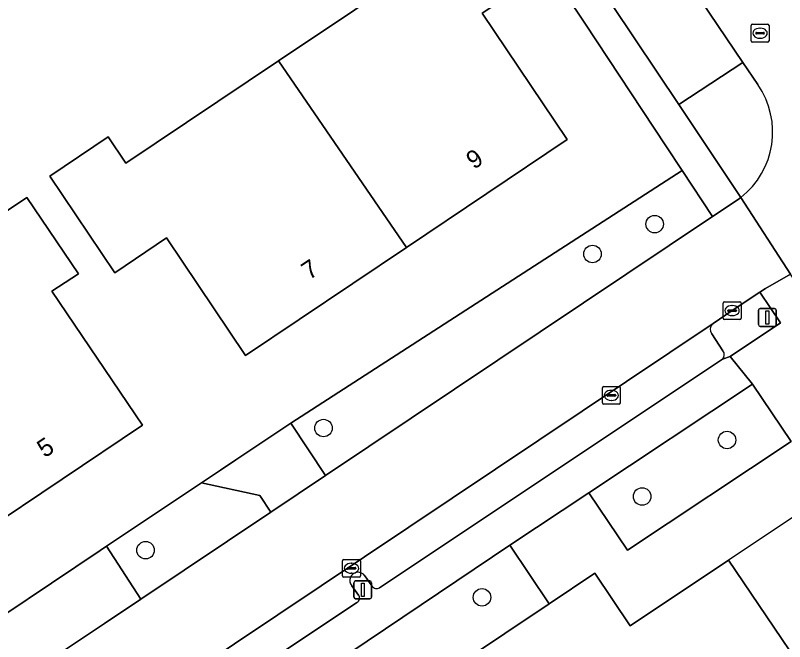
# Model space of a CAD drawing. Extents: x 158793 to 159888, y 384317 to 385256.
# Drawn here: x 158866.24 to 158909.23, y 384582.61 to 384617.61 of the extents above; entities that cross this region are included whole.
import ezdxf

# ---------------------------------------------------------------- set-up
doc = ezdxf.new("R2010")
doc.units = 0
for name, color, linetype in [('IMGEO_Berm_groen', 7, 'Continuous'), ('IMGEO_Boom', 7, 'Continuous'), ('IMGEO_Erf', 7, 'Continuous'), ('IMGEO_Groenvoorziening', 7, 'Continuous'), ('IMGEO_Inrit_open', 7, 'Continuous'), ('IMGEO_Kolk', 7, 'Continuous'), ('IMGEO_Lichtmast', 7, 'Continuous'), ('IMGEO_Pand', 7, 'Continuous'), ('IMGEO_Pand_nummerreeks', 7, 'Continuous'), ('IMGEO_Pand_overbouw', 7, 'Continuous'), ('IMGEO_Parkeervlak_open', 7, 'Continuous'), ('IMGEO_Rijbaan_lokaal_open', 7, 'Continuous'), ('IMGEO_Rioolput', 7, 'Continuous'), ('IMGEO_Voetpad_open', 7, 'Continuous')]:
    doc.layers.add(name, color=color, linetype=linetype)

msp = doc.modelspace()

# ---------------------------------------------------------------- linework, layer by layer
at = {"layer": 'IMGEO_Berm_groen'}
msp.add_lwpolyline([(158907.727, 384613.741), (158906.885, 384614.978), (158903.319, 384612.632), (158906.772, 384607.422)], dxfattribs=at)
msp.add_arc((158903.915, 384611.086), 4.646, 307.9533, 34.8584, dxfattribs=at)
at = {"layer": 'IMGEO_Boom'}
for centre in [(158901.963, 384605.942), (158898.492, 384604.271), (158883.458, 384594.542), (158906.011, 384593.873), (158901.264, 384590.718), (158873.516, 384587.717), (158892.319, 384585.079)]:
    msp.add_circle(centre, 0.489, dxfattribs=at)
at = {"layer": 'IMGEO_Erf'}
msp.add_lwpolyline([(158815.511, 384607.239), (158824.8, 384593.502), (158838.699, 384572.93), (158841.845, 384568.15), (158844.791, 384570.111), (158846.183, 384571.037), (158851.961, 384574.901), (158852.64, 384575.355), (158857.172, 384578.386), (158862.362, 384581.922), (158862.863, 384582.253), (158870.987, 384587.696), (158871.33, 384587.937), (158876.65, 384591.488), (158877.708, 384592.194), (158878.556, 384592.76), (158881.626, 384594.81), (158903.507, 384608.931), (158902.593, 384610.317), (158898.058, 384617.173), (158883.161, 384639.419), (158896.259, 384659.409)], dxfattribs=at)
for points in [[(158890.862, 384623.871), (158894.156, 384618.966), (158892.321, 384617.734), (158897.071, 384610.661), (158888.089, 384604.629), (158879.107, 384598.597), (158874.693, 384605.179), (158871.792, 384603.213), (158868.157, 384608.628), (158871.419, 384610.825), (158872.409, 384609.35), (158880.94, 384615.071), (158889.47, 384620.792), (158888.486, 384622.266)], [(158856.444, 384600.417), (158866.89, 384607.424), (158869.764, 384603.17), (158868.286, 384602.201), (158873.34, 384594.709), (158864.344, 384588.665), (158855.349, 384582.621), (158849.856, 384590.796), (158848.386, 384589.809), (158845.998, 384593.41)]]:
    msp.add_lwpolyline(points, close=True, dxfattribs=at)
at = {"layer": 'IMGEO_Groenvoorziening'}
for points in [[(158905.203, 384606.361), (158903.507, 384608.931), (158881.626, 384594.81), (158883.58, 384591.897)], [(158909.588, 384593.8), (158907.433, 384597), (158898.293, 384590.919), (158900.445, 384587.717)], [(158880.518, 384589.849), (158879.9, 384590.767), (158876.65, 384591.488), (158871.33, 384587.937), (158873.243, 384584.982)], [(158896.066, 384584.721), (158893.869, 384587.99), (158878.954, 384577.951), (158881.101, 384574.689)]]:
    msp.add_lwpolyline(points, close=True, dxfattribs=at)
for points in [[(158907.845, 384602.133), (158906.293, 384601.105), (158905.226, 384600.389), (158905.186, 384600.352)], [(158905.751, 384598.386), (158906.179, 384598.54), (158909.004, 384600.431), (158907.845, 384602.133)], [(158905.152, 384599.809), (158905.78, 384598.862)]]:
    msp.add_lwpolyline(points, dxfattribs=at)
for centre, radius, start, end in [((158905.487, 384600.061), 0.419, 135.8936, 216.9406), ((158905.5, 384598.64), 0.357, 314.6782, 38.349)]:
    msp.add_arc(centre, radius, start, end, dxfattribs=at)
at = {"layer": 'IMGEO_Inrit_open'}
msp.add_lwpolyline([(158871.218, 384583.628), (158873.243, 384584.982), (158871.33, 384587.937), (158870.987, 384587.696), (158862.863, 384582.253), (158862.362, 384581.922), (158864.28, 384578.99), (158865.964, 384580.114), (158866.578, 384580.525)], close=True, dxfattribs=at)
at = {"layer": 'IMGEO_Kolk'}
for p, q in [((158905.792, 384600.679), (158905.792, 384601.531)), ((158905.867, 384601.605), (158906.719, 384601.605)), ((158906.28, 384601.385), (158906.305, 384601.385)), ((158906.793, 384601.531), (158906.793, 384600.679)), ((158906.051, 384601.099), (158906.051, 384601.111)), ((158906.489, 384601.062), (158906.091, 384601.062)), ((158906.094, 384601.148), (158906.492, 384601.148)), ((158906.303, 384600.825), (158906.278, 384600.825)), ((158906.535, 384601.111), (158906.535, 384601.099)), ((158906.719, 384600.605), (158905.867, 384600.605)), ((158899.045, 384595.945), (158899.045, 384596.797)), ((158899.12, 384596.871), (158899.972, 384596.871)), ((158899.533, 384596.651), (158899.558, 384596.651)), ((158900.046, 384596.797), (158900.046, 384595.945)), ((158899.304, 384596.365), (158899.304, 384596.377)), ((158899.742, 384596.328), (158899.344, 384596.328)), ((158899.347, 384596.414), (158899.745, 384596.414)), ((158899.556, 384596.091), (158899.531, 384596.091)), ((158899.788, 384596.377), (158899.788, 384596.365)), ((158899.972, 384595.871), (158899.12, 384595.871)), ((158884.523, 384586.278), (158884.523, 384587.13)), ((158884.598, 384587.204), (158885.45, 384587.204)), ((158885.524, 384587.13), (158885.524, 384586.278)), ((158884.782, 384586.698), (158884.782, 384586.71)), ((158885.22, 384586.661), (158884.822, 384586.661)), ((158884.825, 384586.747), (158885.223, 384586.747)), ((158885.011, 384586.984), (158885.036, 384586.984)), ((158885.266, 384586.71), (158885.266, 384586.698)), ((158885.45, 384586.204), (158884.598, 384586.204)), ((158885.034, 384586.424), (158885.009, 384586.424))]:
    msp.add_line(p, q, dxfattribs=at)
for points in [[(158905.792, 384600.679), (158905.792, 384601.531)], [(158905.867, 384601.605), (158906.719, 384601.605)], [(158906.793, 384601.531), (158906.793, 384600.679)], [(158906.719, 384600.605), (158905.867, 384600.605)], [(158899.045, 384595.945), (158899.045, 384596.797)], [(158899.12, 384596.871), (158899.972, 384596.871)], [(158900.046, 384596.797), (158900.046, 384595.945)], [(158899.972, 384595.871), (158899.12, 384595.871)], [(158884.523, 384586.278), (158884.523, 384587.13)], [(158884.598, 384587.204), (158885.45, 384587.204)], [(158885.524, 384587.13), (158885.524, 384586.278)], [(158885.45, 384586.204), (158884.598, 384586.204)]]:
    msp.add_lwpolyline(points, dxfattribs=at)
for centre, radius, start, end in [((158905.869, 384601.529), 0.0765, 91.552, 178.448), ((158905.869, 384601.529), 0.0765, 91.552, 178.448), ((158906.717, 384601.529), 0.0765, 1.552, 88.448), ((158906.717, 384601.529), 0.0765, 1.552, 88.448), ((158906.091, 384601.108), 0.0403, 85.8775, 175.7526), ((158906.088, 384601.098), 0.0366, 178.938, 274.7102), ((158906.492, 384601.105), 0.043, 264.8664, 352.4533), ((158906.496, 384601.11), 0.0386, 1.7309, 96.639), ((158905.869, 384600.681), 0.0765, 181.552, 268.448), ((158905.869, 384600.681), 0.0765, 181.552, 268.448), ((158906.717, 384600.681), 0.0765, 271.552, 358.448), ((158906.717, 384600.681), 0.0765, 271.552, 358.448), ((158899.122, 384596.795), 0.0765, 91.552, 178.448), ((158899.122, 384596.795), 0.0765, 91.552, 178.448), ((158899.97, 384596.795), 0.0765, 1.552, 88.448), ((158899.97, 384596.795), 0.0765, 1.552, 88.448), ((158899.344, 384596.374), 0.0403, 85.8775, 175.7526), ((158899.341, 384596.364), 0.0366, 178.938, 274.7102), ((158899.745, 384596.371), 0.043, 264.8664, 352.4533), ((158899.749, 384596.376), 0.0386, 1.7309, 96.639), ((158899.122, 384595.947), 0.0765, 181.552, 268.448), ((158899.122, 384595.947), 0.0765, 181.552, 268.448), ((158899.97, 384595.947), 0.0765, 271.552, 358.448), ((158899.97, 384595.947), 0.0765, 271.552, 358.448), ((158884.6, 384587.128), 0.0765, 91.552, 178.448), ((158884.6, 384587.128), 0.0765, 91.552, 178.448), ((158885.448, 384587.128), 0.0765, 1.552, 88.448), ((158885.448, 384587.128), 0.0765, 1.552, 88.448), ((158884.822, 384586.707), 0.0403, 85.8775, 175.7526), ((158884.819, 384586.697), 0.0366, 178.938, 274.7102), ((158885.223, 384586.704), 0.043, 264.8664, 352.4533), ((158885.227, 384586.709), 0.0386, 1.7309, 96.639), ((158884.6, 384586.28), 0.0765, 181.552, 268.448), ((158884.6, 384586.28), 0.0765, 181.552, 268.448), ((158885.448, 384586.28), 0.0765, 271.552, 358.448), ((158885.448, 384586.28), 0.0765, 271.552, 358.448)]:
    msp.add_arc(centre, radius, start, end, dxfattribs=at)
for centre, major_axis, ratio, start_param, end_param in [((158906.279, 384601.105), (-0.387, 0.002), 0.722429, 4.712389, 7.853982), ((158906.304, 384601.105), (-0.39, 0.002), 0.717154, 1.570796, 4.712389), ((158899.532, 384596.371), (-0.387, 0.002), 0.722429, 4.712389, 7.853982), ((158899.557, 384596.371), (-0.39, 0.002), 0.717154, 1.570796, 4.712389), ((158885.01, 384586.704), (-0.387, 0.002), 0.722429, 4.712389, 7.853982), ((158885.035, 384586.704), (-0.39, 0.002), 0.717154, 1.570796, 4.712389)]:
    msp.add_ellipse(centre, major_axis=major_axis, ratio=ratio, start_param=start_param, end_param=end_param, dxfattribs=at)
at = {"layer": 'IMGEO_Lichtmast'}
for p, q in [((158907.866, 384601.226), (158908.656, 384601.226)), ((158908.656, 384601.226), (158907.866, 384601.226)), ((158907.766, 384600.326), (158907.766, 384601.126)), ((158907.766, 384601.126), (158907.766, 384600.326)), ((158908.756, 384601.126), (158908.756, 384600.326)), ((158908.756, 384600.326), (158908.756, 384601.126)), ((158908.656, 384600.226), (158907.866, 384600.226)), ((158907.866, 384600.226), (158908.656, 384600.226)), ((158885.154, 384585.099), (158885.154, 384585.899)), ((158885.154, 384585.899), (158885.154, 384585.099)), ((158885.254, 384585.999), (158886.044, 384585.999)), ((158886.044, 384585.999), (158885.254, 384585.999)), ((158886.144, 384585.899), (158886.144, 384585.099)), ((158886.144, 384585.099), (158886.144, 384585.899)), ((158886.044, 384584.999), (158885.254, 384584.999)), ((158885.254, 384584.999), (158886.044, 384584.999))]:
    msp.add_line(p, q, dxfattribs=at)
for points in [[(158908.186, 384601.101), (158908.336, 384601.101), (158908.336, 384600.351), (158908.186, 384600.351), (158908.186, 384601.101)], [(158885.574, 384585.874), (158885.724, 384585.874), (158885.724, 384585.124), (158885.574, 384585.124), (158885.574, 384585.874)]]:
    msp.add_lwpolyline(points, dxfattribs=at)
for centre, start, end in [((158907.866, 384601.126), 90, 180), ((158907.866, 384601.126), 90, 180), ((158908.656, 384601.126), 0, 90), ((158908.656, 384601.126), 360, 90), ((158907.866, 384600.326), 180, 270), ((158907.866, 384600.326), 180, 270), ((158908.656, 384600.326), 270, 0), ((158908.656, 384600.326), 270, 0), ((158885.254, 384585.899), 90, 180), ((158885.254, 384585.899), 90, 180), ((158886.044, 384585.899), 0, 90), ((158886.044, 384585.899), 360, 90), ((158885.254, 384585.099), 180, 270), ((158885.254, 384585.099), 180, 270), ((158886.044, 384585.099), 270, 0), ((158886.044, 384585.099), 270, 0)]:
    msp.add_arc(centre, 0.1, start, end, dxfattribs=at)
at = {"layer": 'IMGEO_Pand'}
for points in [[(158892.321, 384617.734), (158894.156, 384618.966), (158890.862, 384623.871), (158888.486, 384622.266), (158889.47, 384620.792), (158880.94, 384615.071), (158888.089, 384604.629), (158897.071, 384610.661)], [(158880.94, 384615.071), (158872.409, 384609.35), (158871.419, 384610.825), (158868.157, 384608.628), (158871.792, 384603.213), (158874.693, 384605.179), (158879.107, 384598.597), (158888.089, 384604.629)], [(158868.286, 384602.201), (158869.764, 384603.17), (158866.89, 384607.424), (158856.444, 384600.417), (158864.344, 384588.665), (158873.34, 384594.709)]]:
    msp.add_lwpolyline(points, close=True, dxfattribs=at)
msp.add_lwpolyline([(158907.106, 384572.842), (158909.672, 384568.992), (158915.672, 384572.989), (158912.909, 384577.075), (158906.092, 384587.156), (158900.6, 384583.487), (158898.628, 384586.438), (158896.066, 384584.721), (158881.101, 384574.689), (158876.359, 384571.51), (158872.253, 384568.757), (158870.855, 384567.82), (158868.57, 384566.288), (158860.242, 384560.705), (158859.272, 384560.055), (158858.523, 384559.553)], dxfattribs=at)
at = {"layer": 'IMGEO_Pand_overbouw'}
msp.add_lwpolyline([(158918.255, 384580.636), (158911.49, 384590.763), (158906.092, 384587.156), (158912.909, 384577.075)], close=True, dxfattribs=at)
at = {"layer": 'IMGEO_Parkeervlak_open'}
for points in [[(158905.186, 384600.352), (158905.226, 384600.389), (158854.147, 384566.195), (158854.173, 384566.208), (158854.199, 384566.219), (158854.32, 384566.248)], [(158905.78, 384598.862), (158905.152, 384599.809)], [(158886.591, 384585.621), (158905.751, 384598.386)], [(158885.77, 384586.28), (158886.169, 384585.716)], [(158885.416, 384585.211), (158885.039, 384585.733)], [(158871.178, 384575.348), (158885.328, 384584.798)]]:
    msp.add_lwpolyline(points, dxfattribs=at)
for centre, radius, start, end in [((158905.487, 384600.061), 0.419, 135.8936, 216.9406), ((158905.5, 384598.64), 0.357, 314.6782, 38.349), ((158885.388, 384586.029), 0.457, 33.31, 220.3042), ((158886.427, 384585.876), 0.303, 211.7961, 302.8302), ((158885.187, 384585.044), 0.284, 299.861, 36.0822)]:
    msp.add_arc(centre, radius, start, end, dxfattribs=at)
at = {"layer": 'IMGEO_Rijbaan_lokaal_open'}
for points in [[(158894.038, 384634.089), (158903.158, 384620.5), (158906.885, 384614.978), (158907.727, 384613.741)], [(158905.226, 384600.389), (158906.293, 384601.105), (158907.845, 384602.133), (158908.167, 384602.346), (158909.555, 384603.148), (158906.772, 384607.422), (158906.625, 384607.312), (158905.203, 384606.361), (158883.58, 384591.897), (158880.518, 384589.849), (158873.243, 384584.982), (158871.218, 384583.628), (158866.578, 384580.525)], [(158906.772, 384607.422), (158909.555, 384603.148)], [(158836.541, 384554.422), (158836.668, 384554.507), (158842.356, 384558.296), (158843.187, 384558.851), (158844.83, 384559.95), (158852.903, 384565.347), (158853.914, 384566.031), (158854.099, 384566.166), (158854.147, 384566.195), (158905.226, 384600.389)]]:
    msp.add_lwpolyline(points, dxfattribs=at)
msp.add_lwpolyline([(158881.626, 384594.81), (158878.556, 384592.76), (158877.708, 384592.194), (158876.65, 384591.488), (158879.9, 384590.767), (158880.518, 384589.849), (158883.58, 384591.897)], close=True, dxfattribs=at)
msp.add_arc((158903.915, 384611.086), 4.646, 307.9533, 34.8584, dxfattribs=at)
at = {"layer": 'IMGEO_Rioolput'}
for p, q in [((158907.429, 384617.112), (158908.281, 384617.112)), ((158907.354, 384616.186), (158907.354, 384617.038)), ((158907.842, 384616.892), (158907.867, 384616.892)), ((158908.355, 384617.038), (158908.355, 384616.186)), ((158907.613, 384616.606), (158907.613, 384616.618)), ((158908.051, 384616.569), (158907.653, 384616.569)), ((158907.656, 384616.655), (158908.054, 384616.655)), ((158907.865, 384616.332), (158907.84, 384616.332)), ((158908.097, 384616.618), (158908.097, 384616.606)), ((158908.281, 384616.112), (158907.429, 384616.112))]:
    msp.add_line(p, q, dxfattribs=at)
for points in [[(158907.429, 384617.112), (158908.281, 384617.112)], [(158907.354, 384616.186), (158907.354, 384617.038)], [(158908.355, 384617.038), (158908.355, 384616.186)], [(158908.281, 384616.112), (158907.429, 384616.112)]]:
    msp.add_lwpolyline(points, dxfattribs=at)
for centre, radius, start, end in [((158907.431, 384617.036), 0.0765, 91.552, 178.448), ((158907.431, 384617.036), 0.0765, 91.552, 178.448), ((158908.279, 384617.036), 0.0765, 1.552, 88.448), ((158908.279, 384617.036), 0.0765, 1.552, 88.448), ((158907.653, 384616.615), 0.0403, 85.8775, 175.7526), ((158907.65, 384616.605), 0.0366, 178.938, 274.7102), ((158908.054, 384616.612), 0.043, 264.8664, 352.4533), ((158908.058, 384616.617), 0.0386, 1.7309, 96.639), ((158907.431, 384616.188), 0.0765, 181.552, 268.448), ((158907.431, 384616.188), 0.0765, 181.552, 268.448), ((158908.279, 384616.188), 0.0765, 271.552, 358.448), ((158908.279, 384616.188), 0.0765, 271.552, 358.448)]:
    msp.add_arc(centre, radius, start, end, dxfattribs=at)
for centre, major_axis, ratio, start_param, end_param in [((158907.841, 384616.612), (-0.387, 0.002), 0.722429, 4.712389, 7.853982), ((158907.866, 384616.612), (-0.39, 0.002), 0.717154, 1.570796, 4.712389)]:
    msp.add_ellipse(centre, major_axis=major_axis, ratio=ratio, start_param=start_param, end_param=end_param, dxfattribs=at)
at = {"layer": 'IMGEO_Voetpad_open'}
for points in [[(158883.161, 384639.419), (158898.058, 384617.173), (158902.593, 384610.317), (158903.507, 384608.931), (158905.203, 384606.361), (158906.625, 384607.312), (158906.772, 384607.422), (158903.319, 384612.632), (158899.607, 384618.157)], [(158929.847, 384580.595), (158917.536, 384598.902), (158914.068, 384596.519), (158909.555, 384603.148), (158908.167, 384602.346), (158907.845, 384602.133), (158909.004, 384600.431), (158906.179, 384598.54), (158907.433, 384597), (158909.588, 384593.8), (158900.445, 384587.717), (158898.293, 384590.919), (158893.869, 384587.99), (158896.066, 384584.721), (158898.628, 384586.438), (158900.6, 384583.487), (158906.092, 384587.156), (158912.909, 384577.075)], [(158874.127, 384574.707), (158876.359, 384571.51), (158881.101, 384574.689), (158878.954, 384577.951), (158893.869, 384587.99), (158898.293, 384590.919), (158907.433, 384597), (158906.179, 384598.54), (158905.751, 384598.386), (158886.591, 384585.621)], [(158886.169, 384585.716), (158885.77, 384586.28)], [(158885.039, 384585.733), (158885.416, 384585.211)], [(158885.328, 384584.798), (158871.178, 384575.348)]]:
    msp.add_lwpolyline(points, dxfattribs=at)
msp.add_lwpolyline([(158903.158, 384620.5), (158899.607, 384618.157), (158903.319, 384612.632), (158906.885, 384614.978)], close=True, dxfattribs=at)
for centre, radius, start, end in [((158885.388, 384586.029), 0.457, 33.31, 220.3042), ((158886.427, 384585.876), 0.303, 211.7961, 302.8302), ((158885.187, 384585.044), 0.284, 299.861, 36.0822)]:
    msp.add_arc(centre, radius, start, end, dxfattribs=at)

# ---------------------------------------------------------------- texts
at = {"layer": 'IMGEO_Pand_nummerreeks'}
for s, rotation, p in [('9', 33.884, (158891.864, 384608.971)), ('7', 33.884, (158882.664, 384602.793)), ('5', 33.898, (158867.884, 384592.85))]:
    msp.add_text(s, height=1, rotation=rotation, dxfattribs=at).set_placement(p)

doc.saveas('drawing.dxf')
